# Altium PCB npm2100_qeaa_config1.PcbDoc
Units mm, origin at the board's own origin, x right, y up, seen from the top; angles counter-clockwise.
Board outline 9.5 x 8.5 mm, 2 copper layers (Top Layer, Bottom Layer), stack 1.571 mm thick; 7 components, 10 nets, 29 pads, 21 vias.
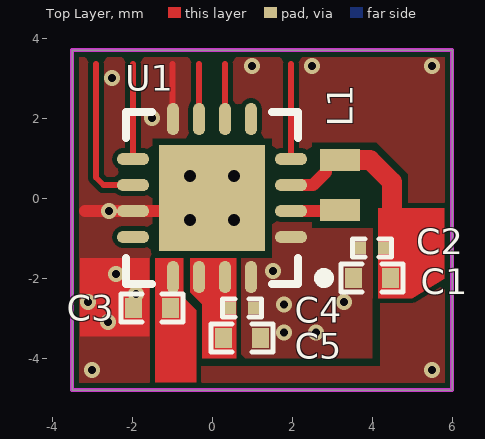
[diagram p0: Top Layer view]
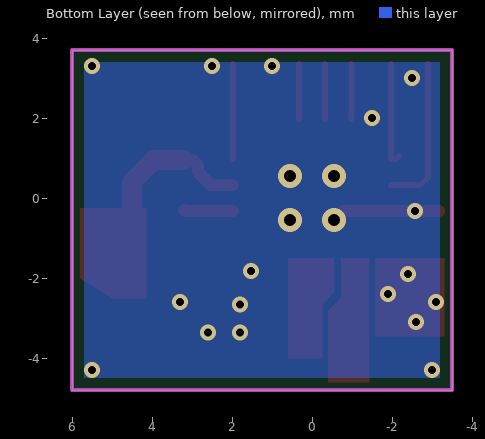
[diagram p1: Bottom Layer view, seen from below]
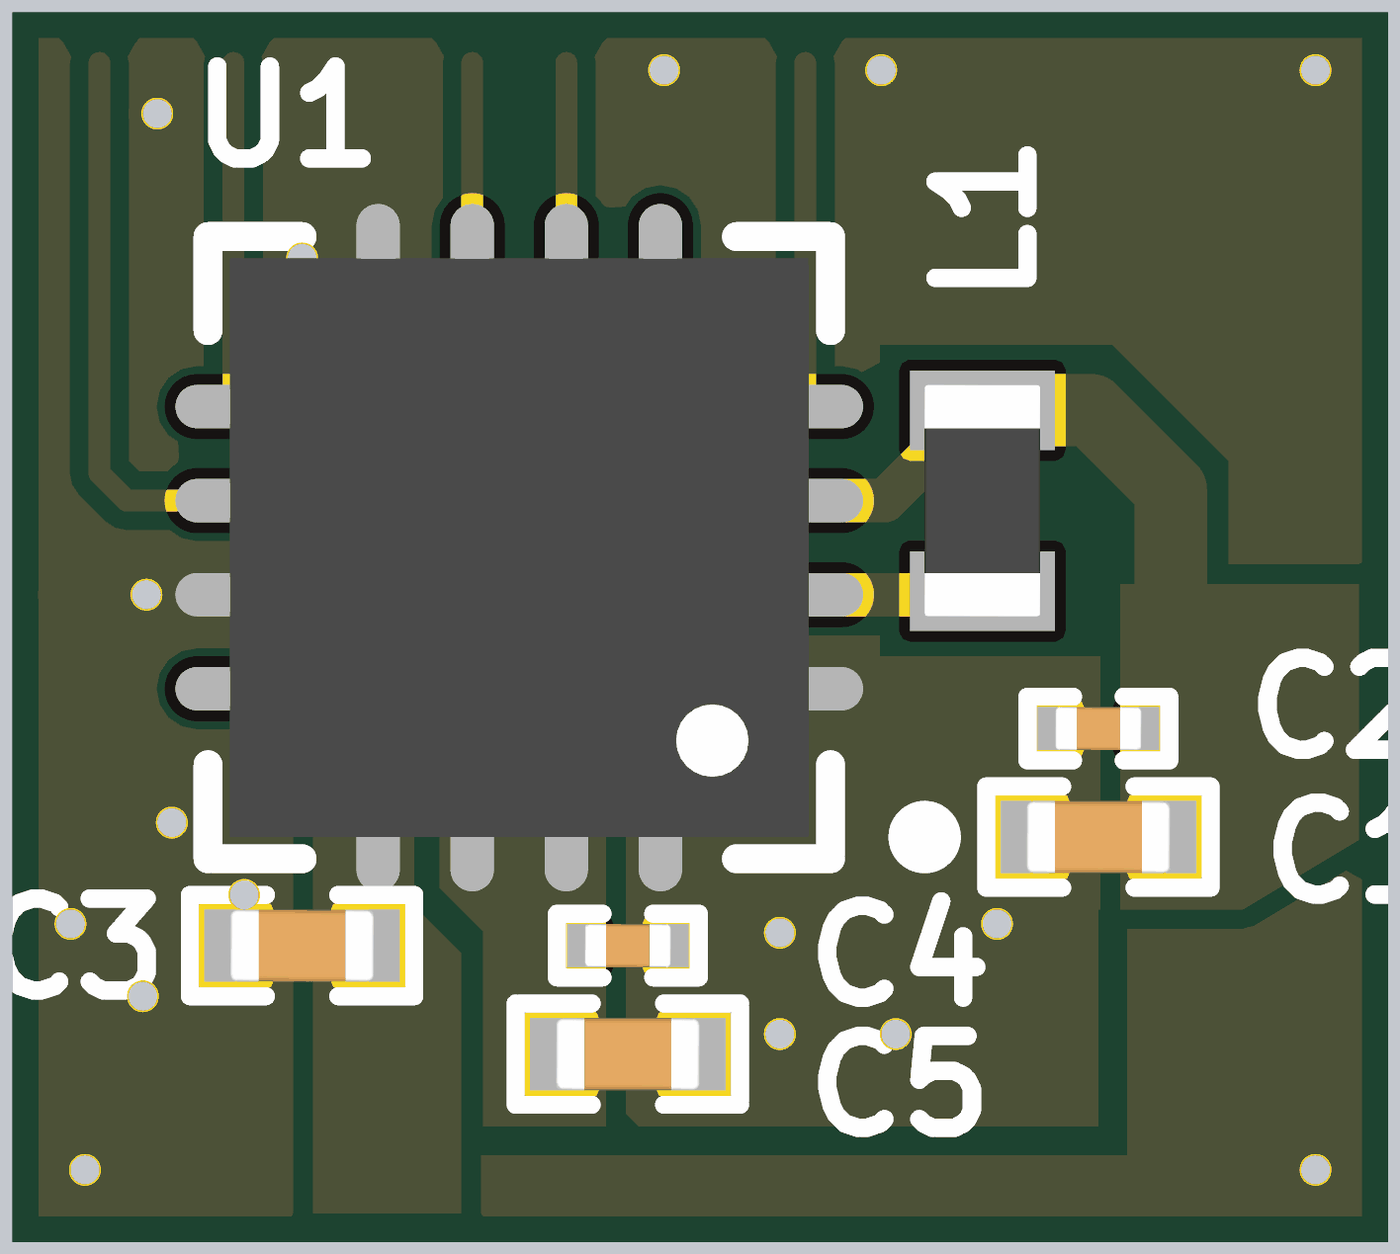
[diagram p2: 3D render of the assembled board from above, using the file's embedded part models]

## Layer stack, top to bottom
Top Solder: solder mask 0.0102, Solder Resist, Dk 3.5
Top Layer: signal copper 0.0356
Dielectric2: core 1.5, FR-4, Dk 4.8
Bottom Layer: signal copper 0.0356
Bottom Solder: solder mask 0.0102, Solder Resist, Dk 3.5

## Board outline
-3.5,-4.8 6,-4.8 6,3.7 -3.5,3.7

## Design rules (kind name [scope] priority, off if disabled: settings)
BoardOutlineClearance [All] p1: gap=0.15 ignorepadtopadclearanceinfootprint=FALSE
Clearance Polygon_Clearance [(InNamedPolygon('Top_Layer-GND')) or (InNamedPolygon('Bottom_Layer-GND')) or (InNamedPolygon('Mid_Layer_1-GND')) or (InNamedPolygon('Mid_Layer_2-GND'))] p1: gap=0.254 ignorepadtopadclearanceinfootprint=FALSE except(0: Arc-Hole Track-Hole SMDPad-Hole THPad-Hole Via-Hole Fill-Hole Poly-Hole Region-Hole Text-Hole)
Clearance [All] p2: gap=0.125 ignorepadtopadclearanceinfootprint=FALSE
ComponentClearance [All] p1 off: gap=0.254 collisioncheckmode=3 verticalgap=0.254 showdistances=FALSE
DiffPairsRouting [All] p1: maxlimit=0.15 minlimit=0.15 mostfreqgap=0.15 toplayer_minwidth=0.15 toplayer_maxwidth=0.15 toplayer_prefwidth=0.15 bottomlayer_minwidth=0.15 bottomlayer_maxwidth=0.15 bottomlayer_prefwidth=0.15 impedanceprofiledriven=TRUE maxuncoupledlength=12.7
FabricationTestPointUsage TestPointUsage [All] p1: valid=0 allowmultiple=FALSE
FabricationTestpoint Testpoint [All] p1: side=3 testpointundercomponent=TRUE minsize=1.016 maxsize=2.54 preferedsize=1.524 minholesize=0 maxholesize=1.016 preferedholesize=0.813 testpointgrid=0.025 allowsidetop=TRUE allowsidebottom=TRUE usegrid=TRUE gridtolerance=0
Height [All] p1 off: minheight=0 maxheight=25.4 prefheight=12.7
HoleSize [All] p1: absolutevalues=TRUE maxlimit=5 minlimit=0.1 maxpercent=80.000 minpercent=20.000
MinimumAnnularRing [All] p1 off: minimumring=0.1
MinimumSolderMaskSliver [All] p1: minsoldermaskwidth=0.03
PolygonConnect PolygonConnect_GND [InNet('GND')] p1: connectstyle=Direct reliefconductorwidth=0.254 reliefentries=4 polygonreliefangle="90 Angle" airgapwidth=0.254
PolygonConnect [All] p2: connectstyle=Direct reliefconductorwidth=0.254 reliefentries=4 polygonreliefangle="90 Angle" airgapwidth=0.254
RoutingVias [All] p1: holewidth=0.3 width=0.6 viastyle="Through Hole" minholewidth=0.2 minwidth=0.4 maxholewidth=0.5 maxwidth=1
ShortCircuit ShortCircuit_PVSS [InNet('PVSS1') or InNet('PVSS2') or InNet('PVSS3') vs InNet('GND')] p1: allowed=TRUE
ShortCircuit [All] p2: allowed=FALSE
SilkToSilkClearance [All] p1: silktosilkclearance=0.1
SilkToSolderMaskClearance SilkscreenOverComponentPads [IsPad] p1: minsilkscreentomaskgap=0.254 clearancetoexposedcopper=TRUE
SolderMaskExpansion SolderMaskExpansion_Vias [IsVia] p1: expansion=0.102 istentingtop=TRUE
SolderMaskExpansion [All] p2: expansion=0.075 istentingtop=FALSE
UnRoutedNet [All] p1: checkbadconnections=TRUE
Width [All] p1: maxlimit=2 minlimit=0.12 preferedwidth=0.3
19 further rules are at their usual default settings.

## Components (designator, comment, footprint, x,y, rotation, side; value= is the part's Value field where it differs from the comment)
C1 "10µF" CAPC1005X04L_C2 4,-2 r0 top
C2 "1nF" CAPC0603X03L_C 4,-1.25 r0 top
C3 "2.2µF" CAPC1005X04L_C2 -1.5,-2.75 r0 top
C4 "1nF" CAPC0603X03L_C 0.75,-2.75 r180 top
C5 "10µF" CAPC1005X04L_C2 0.75,-3.5 r180 top
L1 "2.2µH" INDC1608X06L_C2 3.199,0.325 r270 top
U1 "nPM2100-QEAA" QFN65P400X400X65_HS-17N 0,0 r180 top

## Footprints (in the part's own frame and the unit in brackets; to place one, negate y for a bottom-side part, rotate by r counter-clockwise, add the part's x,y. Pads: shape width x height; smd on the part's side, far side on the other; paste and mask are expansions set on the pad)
CAPC0603X03L_C [mm] "Chip Capacitor, 2-Leads, Body 0.6x0.3mm, IPC High Density"
  rect 0.27x0.3 smd mask+0.05: 1(-0.285,0) 2(0.285,0)
  silkscreen extent -0.49,-0.22 0.49,0.22, body extent -0.3,-0.15 0.3,0.15, height 0.3
CAPC1005X04L_C2 [mm] "Chip Capacitor, 2-Leads, Body 1.0x0.5mm, IPC High Density"
  rect 0.425x0.5 smd mask+0.05: 1(-0.463,0) 2(0.463,0)
  silkscreen extent -0.77,-0.35 0.77,0.35, body extent -0.5,-0.25 0.5,0.25, height 0.5
INDC1608X06L_C2 [mm] "Chip Inductor, 2-Leads, Body 1.6x0.8mm, IPC High Density"
  rect 0.55x1 smd: 1(-0.625,0) 2(0.625,0)
  body extent -0.8,-0.4 0.8,0.4, height 0.8
QFN65P400X400X65_HS-17N [mm] "QFN, 16-Leads, Body 4.00x4.00mm, Pitch 0.65mm, Thermal Pad 2.65x2.65mm, IPC Medium Density"
  oval 0.8x0.3 smd mask+0: 1(-1.975,0.975) 11(1.975,0.325)
  oval 0.8x0.3 smd: 2(-1.975,0.325) 3(-1.975,-0.325) 4(-1.975,-0.975) 9(1.975,-0.975) 10(1.975,-0.325) 12(1.975,0.975)
  oval 0.3x0.8 smd: 5(-0.975,-1.975) 6(-0.325,-1.975) 7(0.325,-1.975)
  oval 0.3x0.8 smd mask+0: 8(0.975,-1.975) 13(0.975,1.975) 14(0.325,1.975) 15(-0.325,1.975) 16(-0.975,1.975)
  rect 2.65x2.65 smd: 17(0,0)
  silkscreen extent -2.93,-2.15 2.15,2.15, body extent -2,-2 2,2, height 0.65

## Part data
C1 C5: library part C0402-10µ-6.3V-X5R-GRM155R60J106ME05D, "Capacitor, X5R, ±20%, 6.3V", Manufacturer=Murata, Manufacturer Part Number=GRM155R60J106ME05D, Part number IPS=N.A., Part number NEMS=100200554, Supplier Part Number 1=490-GRM155R60J106ME05DTR-ND
C2 C4: library part C0201-1n0-50V-X7R, "Capacitor, X7R, ±10pF, 50V", Manufacturer=Murata, Manufacturer Part Number=GRM033R71H102KA12D, Part number IPS=N.A., Part number NEMS=100200404, Supplier Part Number 1=490-10682-1-ND
C3: library part C0402-2µ2-6.3V-X5R-GRM155R60J225ME01D, "Capacitor, X5R, ±20%, 6.3V", Manufacturer=Murata, Manufacturer Part Number=GRM155R60J225ME01D, Part number IPS=N.A., Part number NEMS=100200557, Supplier Part Number 1=490-GRM155R60J225ME01DTR-ND
L1: library part L0603-2µ2-1.8A-237mOhm-LSCNB1608HKT2R2MD, "Unshielded Multilayer Inductor, 1.2A, ±20%, 137.5mOhm", Manufacturer="Taiyo Yuden", Manufacturer Part Number=LSCNB1608HKT2R2MD, Part number IPS=N.A., Part number NEMS=100300450, Supplier Part Number 1=587-LSCNB1608HKT2R2MDTR-ND
U1: "Boost converter companion PMIC for maximum energy extraction of primary (no-rechargeable) batteries", Manufacturer="Nordic Semiconductor", Manufacturer Part Number=nPM2100_QEAA, Part number IPS=N.A., Part number NEMS=102000298

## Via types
v1: diameter 0.4, hole 0.2, Top Layer to Bottom Layer, tented both sides, 17 vias
v2: diameter 0.61, hole 0.305, Top Layer to Bottom Layer, tented both sides, 4 vias

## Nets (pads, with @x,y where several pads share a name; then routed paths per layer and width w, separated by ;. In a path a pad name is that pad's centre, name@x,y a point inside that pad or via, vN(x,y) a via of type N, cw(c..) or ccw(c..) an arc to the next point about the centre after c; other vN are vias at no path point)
GND: C1.1 C2.1 C3.1 C4.1 C5.1 U1.1 U1.8 U1.11 U1.16 U1.17 | length 4.1
  Top Layer w0.15: -0.987,3.35 -0.987,1.987 U1.8
  Top Layer w0.3: -3.175,-0.325 -0.775,-0.325 v2(-0.55,-0.55)
  other v1: -3,-4.3 5.5,-4.3 1.8,-3.362 2.6,-3.362 -2.6,-3.1 1.8,-2.662 -3.1,-2.6 3.3,-2.6 -1.9,-2.4 -2.4,-1.9 1.525,-1.825 -2.575,-0.325 -1.5,2 -2.5,3 1,3.3 2.5,3.3 5.5,3.3
  other v2: 0.55,-0.55 -0.55,0.55 0.55,0.55
GPIO1: U1.9 | length 2.6
  Top Layer w0.15: U1.9@-2.175,1.044 -2.106,0.975 U1.9 -1.975,3.35
PG/RESET: U1.10 | length 3.8
  Top Layer w0.15: -2.9,3.35 -2.9,0.513 -2.712,0.325 U1.10
SCL: U1.7 | length 1.4
  Top Layer w0.15: U1.7 -0.325,3.35
SDA: U1.6 | length 1.4
  Top Layer w0.15: U1.6 0.325,3.35
SHPHLD: U1.4 | length 2.4
  Top Layer w0.15: U1.4 1.975,3.35
SW: L1.2 U1.2 | length 1.2
  Top Layer w0.3: U1.2 3.174,-0.325 L1.2
VBAT: C1.2 C2.2 L1.1 U1.3 | length 5.7
  Top Layer w0.3: U1.3 2.525,0.325 2.849,0.649 2.849,0.825 2.974,0.95 L1.1
  Top Layer w0.5: L1.1 3.95,0.95 4.5,0.4 4.5,-1.25 C1.2@4.5,-2.2
VINT: C4.2 C5.2 U1.14 U1.15
VOUT: C3.2 U1.13
pads on no net: U1.5 U1.12

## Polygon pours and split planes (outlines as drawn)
GND on Bottom Layer "Bottom_Layer-GND" (solid, remove dead copper, pour order 7): -5,-5 -5,5 7.5,5 7.5,-5
GND on Top Layer "NONET_L-01_P-001" (solid, pour order 8): -3.5,-4.8 6,-4.8 6,3.7 -3.5,3.7

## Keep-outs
Keep-Out Layer:
  the board outline again, w0.1

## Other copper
Top Layer:
  pour cut-out: 4,-2.5 4,-4 -0.3,-4 -0.3,-4.2 4.2,-4.2 4.2,-2.5
  region net VBAT: 5.8,-0.25 4.15,-0.25 4.15,-2.5 5,-2.5 5.8,-2.02
  pour cut-out: -1.5,1.5 -1.5,-1.5 1.5,-1.5 1.5,1.5
  region net VINT: 0.6,-4 0.6,-1.5 -0.55,-1.5 -0.55,-2.35 -0.25,-2.65 -0.25,-4
  region net VOUT: -0.4,-4.6 -0.4,-2.8 -0.725,-2.475 -0.725,-1.5 -1.425,-1.5 -1.425,-4.6
  region net GND: -3.3,-3.462 -3.3,-1.5 -1.575,-1.5 -1.575,-3.462
  pour cut-out: 2.492,1.4 4.1,1.4 4.9,0.6 4.9,-0.75 2.492,-0.75

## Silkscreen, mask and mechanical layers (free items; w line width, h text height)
Mechanical 1:
  the board outline again, w0.2

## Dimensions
-3.5,-4.8 to 6,-4.8 on Mechanical 3
6,3.7 to 6,-4.8 on Mechanical 3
